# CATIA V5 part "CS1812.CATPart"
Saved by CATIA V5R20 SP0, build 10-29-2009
Part number: CS1812
Revision: 5
Definition: design
Nomenclature: CS1812
Source: made
Description: NOT SPECIFIED
Bounding box of the stored display mesh (mm): x -11.818 to 12, y -12 to 12, z -22 to 6
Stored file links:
  C:\Users\Raffaele\Desktop\3D X SITO CF\BOLEX\20-TILTED COLUMN SUPPORT\CS1812.CATPart
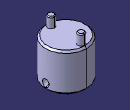
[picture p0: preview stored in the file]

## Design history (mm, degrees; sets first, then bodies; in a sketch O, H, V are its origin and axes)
Body1 "MANIFOLD_SOLID_BREP #683" (main body)
  Solid1: solid without history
